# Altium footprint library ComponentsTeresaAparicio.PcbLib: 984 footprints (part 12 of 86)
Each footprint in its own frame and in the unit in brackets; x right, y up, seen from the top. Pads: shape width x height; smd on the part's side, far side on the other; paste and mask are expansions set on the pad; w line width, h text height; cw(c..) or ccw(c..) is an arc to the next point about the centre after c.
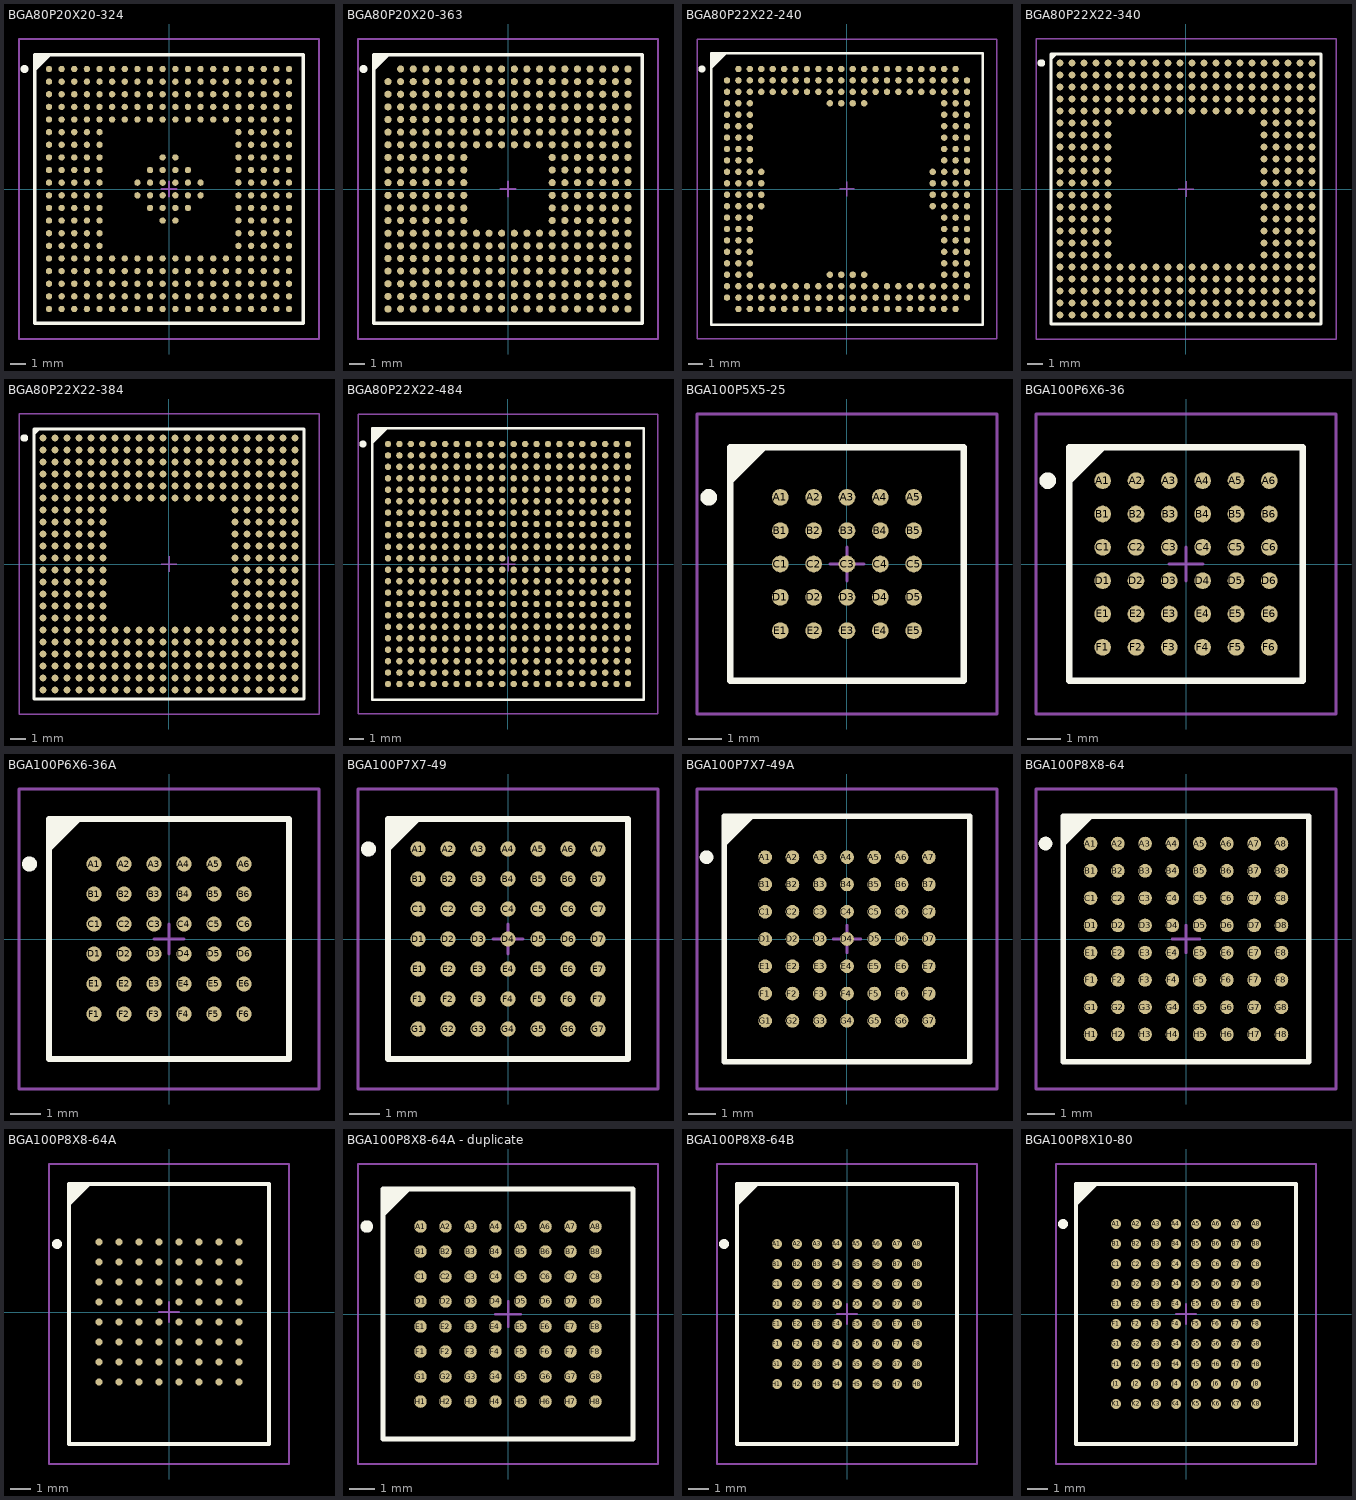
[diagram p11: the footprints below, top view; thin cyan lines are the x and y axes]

## BGA80P20X20-324 [mm] "324-Ball Chip Array Ball Grid Array"
height 1.7
pads (324):
  round 0.4 smd: A1(-7.6,7.6) A2(-6.8,7.6) A3(-6,7.6) A4(-5.2,7.6) A5(-4.4,7.6) A6(-3.6,7.6) A7(-2.8,7.6) A8(-2,7.6) A9(-1.2,7.6) A10(-0.4,7.6) A11(0.4,7.6) A12(1.2,7.6) A13(2,7.6) A14(2.8,7.6) A15(3.6,7.6) A16(4.4,7.6) A17(5.2,7.6) A18(6,7.6) A19(6.8,7.6) A20(7.6,7.6) B1(-7.6,6.8) B2(-6.8,6.8) B3(-6,6.8) B4(-5.2,6.8) B5(-4.4,6.8) B6(-3.6,6.8) B7(-2.8,6.8) B8(-2,6.8) B9(-1.2,6.8) B10(-0.4,6.8) B11(0.4,6.8) B12(1.2,6.8) B13(2,6.8) B14(2.8,6.8) B15(3.6,6.8) B16(4.4,6.8) B17(5.2,6.8) B18(6,6.8) B19(6.8,6.8) B20(7.6,6.8) C1(-7.6,6) C2(-6.8,6) C3(-6,6) C4(-5.2,6) C5(-4.4,6) C6(-3.6,6) C7(-2.8,6) C8(-2,6) C9(-1.2,6) C10(-0.4,6) C11(0.4,6) C12(1.2,6) C13(2,6) C14(2.8,6) C15(3.6,6) C16(4.4,6) C17(5.2,6) C18(6,6) C19(6.8,6) C20(7.6,6) D1(-7.6,5.2) D2(-6.8,5.2) D3(-6,5.2) D4(-5.2,5.2) D5(-4.4,5.2) D6(-3.6,5.2) D7(-2.8,5.2) D8(-2,5.2) D9(-1.2,5.2) D10(-0.4,5.2) D11(0.4,5.2) D12(1.2,5.2) D13(2,5.2) D14(2.8,5.2) D15(3.6,5.2) D16(4.4,5.2) D17(5.2,5.2) D18(6,5.2) D19(6.8,5.2) D20(7.6,5.2) E1(-7.6,4.4) E2(-6.8,4.4) E3(-6,4.4) E4(-5.2,4.4) E5(-4.4,4.4) E6(-3.6,4.4) E7(-2.8,4.4) E8(-2,4.4) E9(-1.2,4.4) E10(-0.4,4.4) E11(0.4,4.4) E12(1.2,4.4) E13(2,4.4) E14(2.8,4.4) E15(3.6,4.4) E16(4.4,4.4) E17(5.2,4.4) E18(6,4.4) E19(6.8,4.4) E20(7.6,4.4) F1(-7.6,3.6) F2(-6.8,3.6) F3(-6,3.6) F4(-5.2,3.6) F5(-4.4,3.6) F16(4.4,3.6) F17(5.2,3.6) F18(6,3.6) F19(6.8,3.6) F20(7.6,3.6) G1(-7.6,2.8) G2(-6.8,2.8) G3(-6,2.8) G4(-5.2,2.8) G5(-4.4,2.8) G16(4.4,2.8) G17(5.2,2.8) G18(6,2.8) G19(6.8,2.8) G20(7.6,2.8) H1(-7.6,2) H2(-6.8,2) H3(-6,2) H4(-5.2,2) H5(-4.4,2) H10(-0.4,2) H11(0.4,2) H16(4.4,2) H17(5.2,2) H18(6,2) H19(6.8,2) H20(7.6,2) J1(-7.6,1.2) J2(-6.8,1.2) J3(-6,1.2) J4(-5.2,1.2) J5(-4.4,1.2) J9(-1.2,1.2) J10(-0.4,1.2) J11(0.4,1.2) J12(1.2,1.2) J16(4.4,1.2) J17(5.2,1.2) J18(6,1.2) J19(6.8,1.2) J20(7.6,1.2) K1(-7.6,0.4) K2(-6.8,0.4) K3(-6,0.4) K4(-5.2,0.4) K5(-4.4,0.4) K8(-2,0.4) K9(-1.2,0.4) K10(-0.4,0.4) K11(0.4,0.4) K12(1.2,0.4) K13(2,0.4) K16(4.4,0.4) K17(5.2,0.4) K18(6,0.4) K19(6.8,0.4) K20(7.6,0.4) L1(-7.6,-0.4) L2(-6.8,-0.4) L3(-6,-0.4) L4(-5.2,-0.4) L5(-4.4,-0.4) L8(-2,-0.4) L9(-1.2,-0.4) L10(-0.4,-0.4) L11(0.4,-0.4) L12(1.2,-0.4) L13(2,-0.4) L16(4.4,-0.4) L17(5.2,-0.4) L18(6,-0.4) L19(6.8,-0.4) L20(7.6,-0.4) M1(-7.6,-1.2) M2(-6.8,-1.2) M3(-6,-1.2) M4(-5.2,-1.2) M5(-4.4,-1.2) M9(-1.2,-1.2) M10(-0.4,-1.2) M11(0.4,-1.2) M12(1.2,-1.2) M16(4.4,-1.2) M17(5.2,-1.2) M18(6,-1.2) M19(6.8,-1.2) M20(7.6,-1.2) N1(-7.6,-2) N2(-6.8,-2) N3(-6,-2) N4(-5.2,-2) N5(-4.4,-2) N10(-0.4,-2) N11(0.4,-2) N16(4.4,-2) N17(5.2,-2) N18(6,-2) N19(6.8,-2) N20(7.6,-2) P1(-7.6,-2.8) P2(-6.8,-2.8) P3(-6,-2.8) P4(-5.2,-2.8) P5(-4.4,-2.8) P16(4.4,-2.8) P17(5.2,-2.8) P18(6,-2.8) P19(6.8,-2.8) P20(7.6,-2.8) R1(-7.6,-3.6) R2(-6.8,-3.6) R3(-6,-3.6) R4(-5.2,-3.6) R5(-4.4,-3.6) R16(4.4,-3.6) R17(5.2,-3.6) R18(6,-3.6) R19(6.8,-3.6) R20(7.6,-3.6) T1(-7.6,-4.4) T2(-6.8,-4.4) T3(-6,-4.4) T4(-5.2,-4.4) T5(-4.4,-4.4) T6(-3.6,-4.4) T7(-2.8,-4.4) T8(-2,-4.4) T9(-1.2,-4.4) T10(-0.4,-4.4) T11(0.4,-4.4) T12(1.2,-4.4) T13(2,-4.4) T14(2.8,-4.4) T15(3.6,-4.4) T16(4.4,-4.4) T17(5.2,-4.4) T18(6,-4.4) T19(6.8,-4.4) T20(7.6,-4.4) U1(-7.6,-5.2) U2(-6.8,-5.2) U3(-6,-5.2) U4(-5.2,-5.2) U5(-4.4,-5.2) U6(-3.6,-5.2) U7(-2.8,-5.2) U8(-2,-5.2) U9(-1.2,-5.2) U10(-0.4,-5.2) U11(0.4,-5.2) U12(1.2,-5.2) U13(2,-5.2) U14(2.8,-5.2) U15(3.6,-5.2) U16(4.4,-5.2) U17(5.2,-5.2) U18(6,-5.2) U19(6.8,-5.2) U20(7.6,-5.2) V1(-7.6,-6) V2(-6.8,-6) V3(-6,-6) V4(-5.2,-6) V5(-4.4,-6) V6(-3.6,-6) V7(-2.8,-6) V8(-2,-6) V9(-1.2,-6) V10(-0.4,-6) V11(0.4,-6) V12(1.2,-6) V13(2,-6) V14(2.8,-6) V15(3.6,-6) V16(4.4,-6) V17(5.2,-6) V18(6,-6) V19(6.8,-6) V20(7.6,-6) W1(-7.6,-6.8) W2(-6.8,-6.8) W3(-6,-6.8) W4(-5.2,-6.8) W5(-4.4,-6.8) W6(-3.6,-6.8) W7(-2.8,-6.8) W8(-2,-6.8) W9(-1.2,-6.8) W10(-0.4,-6.8) W11(0.4,-6.8) W12(1.2,-6.8) W13(2,-6.8) W14(2.8,-6.8) W15(3.6,-6.8) W16(4.4,-6.8) W17(5.2,-6.8) W18(6,-6.8) W19(6.8,-6.8) W20(7.6,-6.8) Y1(-7.6,-7.6) Y2(-6.8,-7.6) Y3(-6,-7.6) Y4(-5.2,-7.6) Y5(-4.4,-7.6) Y6(-3.6,-7.6) Y7(-2.8,-7.6) Y8(-2,-7.6) Y9(-1.2,-7.6) Y10(-0.4,-7.6) Y11(0.4,-7.6) Y12(1.2,-7.6) Y13(2,-7.6) Y14(2.8,-7.6) Y15(3.6,-7.6) Y16(4.4,-7.6) Y17(5.2,-7.6) Y18(6,-7.6) Y19(6.8,-7.6) Y20(7.6,-7.6)
Top Overlay:
  circle w0.25: c-9.15,7.6 r0.125
  region: -7.549,8.5 -8.5,7.549 -8.5,8.5
  lines w0.2: -8.5,7.549 -7.549,8.5 ; -8.5,-8.5 -8.5,8.5 8.5,8.5 8.5,-8.5 -8.5,-8.5
Mechanical 13:
  lines w0.1: -8.5,-8.5 -8.5,8.5 8.5,8.5 8.5,-8.5 -8.5,-8.5
Mechanical 15:
  lines w0.1: -0.5,0 0.5,0 ; 0,-0.5 0,0.5 ; -9.5,-9.5 -9.5,9.5 9.5,9.5 9.5,-9.5 -9.5,-9.5
3D body: height 1.7, standoff 0, extent -8.5,-8.5 8.5,8.5

## BGA80P20X20-363 [mm] "363-Ball Flip Chip Fine Pitch Ball Grid Array (SF363)"
height 1.99
pads (363):
  round 0.45 smd: A2(-6.8,7.6) A3(-6,7.6) A4(-5.2,7.6) A5(-4.4,7.6) A6(-3.6,7.6) A7(-2.8,7.6) A8(-2,7.6) A9(-1.2,7.6) A10(-0.4,7.6) A11(0.4,7.6) A12(1.2,7.6) A13(2,7.6) A14(2.8,7.6) A15(3.6,7.6) A16(4.4,7.6) A17(5.2,7.6) A18(6,7.6) A19(6.8,7.6) A20(7.6,7.6) B1(-7.6,6.8) B2(-6.8,6.8) B3(-6,6.8) B4(-5.2,6.8) B5(-4.4,6.8) B6(-3.6,6.8) B7(-2.8,6.8) B8(-2,6.8) B9(-1.2,6.8) B10(-0.4,6.8) B11(0.4,6.8) B12(1.2,6.8) B13(2,6.8) B14(2.8,6.8) B15(3.6,6.8) B16(4.4,6.8) B17(5.2,6.8) B18(6,6.8) B19(6.8,6.8) B20(7.6,6.8) C1(-7.6,6) C2(-6.8,6) C3(-6,6) C4(-5.2,6) C5(-4.4,6) C6(-3.6,6) C7(-2.8,6) C8(-2,6) C9(-1.2,6) C10(-0.4,6) C11(0.4,6) C12(1.2,6) C13(2,6) C14(2.8,6) C15(3.6,6) C16(4.4,6) C17(5.2,6) C18(6,6) C19(6.8,6) C20(7.6,6) D1(-7.6,5.2) D2(-6.8,5.2) D3(-6,5.2) D4(-5.2,5.2) D5(-4.4,5.2) D6(-3.6,5.2) D7(-2.8,5.2) D8(-2,5.2) D9(-1.2,5.2) D10(-0.4,5.2) D11(0.4,5.2) D12(1.2,5.2) D13(2,5.2) D14(2.8,5.2) D15(3.6,5.2) D16(4.4,5.2) D17(5.2,5.2) D18(6,5.2) D19(6.8,5.2) D20(7.6,5.2) E1(-7.6,4.4) E2(-6.8,4.4) E3(-6,4.4) E4(-5.2,4.4) E5(-4.4,4.4) E6(-3.6,4.4) E7(-2.8,4.4) E8(-2,4.4) E9(-1.2,4.4) E10(-0.4,4.4) E11(0.4,4.4) E12(1.2,4.4) E13(2,4.4) E14(2.8,4.4) E15(3.6,4.4) E16(4.4,4.4) E17(5.2,4.4) E18(6,4.4) E19(6.8,4.4) E20(7.6,4.4) F1(-7.6,3.6) F2(-6.8,3.6) F3(-6,3.6) F4(-5.2,3.6) F5(-4.4,3.6) F6(-3.6,3.6) F7(-2.8,3.6) F8(-2,3.6) F9(-1.2,3.6) F10(-0.4,3.6) F11(0.4,3.6) F12(1.2,3.6) F13(2,3.6) F14(2.8,3.6) F15(3.6,3.6) F16(4.4,3.6) F17(5.2,3.6) F18(6,3.6) F19(6.8,3.6) F20(7.6,3.6) G1(-7.6,2.8) G2(-6.8,2.8) G3(-6,2.8) G4(-5.2,2.8) G5(-4.4,2.8) G6(-3.6,2.8) G7(-2.8,2.8) G8(-2,2.8) G9(-1.2,2.8) G10(-0.4,2.8) G11(0.4,2.8) G12(1.2,2.8) G13(2,2.8) G14(2.8,2.8) G15(3.6,2.8) G16(4.4,2.8) G17(5.2,2.8) G18(6,2.8) G19(6.8,2.8) G20(7.6,2.8) H1(-7.6,2) H2(-6.8,2) H3(-6,2) H4(-5.2,2) H5(-4.4,2) H6(-3.6,2) H7(-2.8,2) H14(2.8,2) H15(3.6,2) H16(4.4,2) H17(5.2,2) H18(6,2) H19(6.8,2) H20(7.6,2) J1(-7.6,1.2) J2(-6.8,1.2) J3(-6,1.2) J4(-5.2,1.2) J5(-4.4,1.2) J6(-3.6,1.2) J7(-2.8,1.2) J14(2.8,1.2) J15(3.6,1.2) J16(4.4,1.2) J17(5.2,1.2) J18(6,1.2) J19(6.8,1.2) J20(7.6,1.2) K1(-7.6,0.4) K2(-6.8,0.4) K3(-6,0.4) K4(-5.2,0.4) K5(-4.4,0.4) K6(-3.6,0.4) K7(-2.8,0.4) K14(2.8,0.4) K15(3.6,0.4) K16(4.4,0.4) K17(5.2,0.4) K18(6,0.4) K19(6.8,0.4) K20(7.6,0.4) L1(-7.6,-0.4) L2(-6.8,-0.4) L3(-6,-0.4) L4(-5.2,-0.4) L5(-4.4,-0.4) L6(-3.6,-0.4) L7(-2.8,-0.4) L14(2.8,-0.4) L15(3.6,-0.4) L16(4.4,-0.4) L17(5.2,-0.4) L18(6,-0.4) L19(6.8,-0.4) L20(7.6,-0.4) M1(-7.6,-1.2) M2(-6.8,-1.2) M3(-6,-1.2) M4(-5.2,-1.2) M5(-4.4,-1.2) M6(-3.6,-1.2) M7(-2.8,-1.2) M14(2.8,-1.2) M15(3.6,-1.2) M16(4.4,-1.2) M17(5.2,-1.2) M18(6,-1.2) M19(6.8,-1.2) M20(7.6,-1.2) N1(-7.6,-2) N2(-6.8,-2) N3(-6,-2) N4(-5.2,-2) N5(-4.4,-2) N6(-3.6,-2) N7(-2.8,-2) N14(2.8,-2) N15(3.6,-2) N16(4.4,-2) N17(5.2,-2) N18(6,-2) N19(6.8,-2) N20(7.6,-2) P1(-7.6,-2.8) P2(-6.8,-2.8) P3(-6,-2.8) P4(-5.2,-2.8) P5(-4.4,-2.8) P6(-3.6,-2.8) P7(-2.8,-2.8) P8(-2,-2.8) P9(-1.2,-2.8) P10(-0.4,-2.8) P11(0.4,-2.8) P12(1.2,-2.8) P13(2,-2.8) P14(2.8,-2.8) P15(3.6,-2.8) P16(4.4,-2.8) P17(5.2,-2.8) P18(6,-2.8) P19(6.8,-2.8) P20(7.6,-2.8) R1(-7.6,-3.6) R2(-6.8,-3.6) R3(-6,-3.6) R4(-5.2,-3.6) R5(-4.4,-3.6) R6(-3.6,-3.6) R7(-2.8,-3.6) R8(-2,-3.6) R9(-1.2,-3.6) R10(-0.4,-3.6) R11(0.4,-3.6) R12(1.2,-3.6) R13(2,-3.6) R14(2.8,-3.6) R15(3.6,-3.6) R16(4.4,-3.6) R17(5.2,-3.6) R18(6,-3.6) R19(6.8,-3.6) R20(7.6,-3.6) T1(-7.6,-4.4) T2(-6.8,-4.4) T3(-6,-4.4) T4(-5.2,-4.4) T5(-4.4,-4.4) T6(-3.6,-4.4) T7(-2.8,-4.4) T8(-2,-4.4) T9(-1.2,-4.4) T10(-0.4,-4.4) T11(0.4,-4.4) T12(1.2,-4.4) T13(2,-4.4) T14(2.8,-4.4) T15(3.6,-4.4) T16(4.4,-4.4) T17(5.2,-4.4) T18(6,-4.4) T19(6.8,-4.4) T20(7.6,-4.4) U1(-7.6,-5.2) U2(-6.8,-5.2) U3(-6,-5.2) U4(-5.2,-5.2) U5(-4.4,-5.2) U6(-3.6,-5.2) U7(-2.8,-5.2) U8(-2,-5.2) U9(-1.2,-5.2) U10(-0.4,-5.2) U11(0.4,-5.2) U12(1.2,-5.2) U13(2,-5.2) U14(2.8,-5.2) U15(3.6,-5.2) U16(4.4,-5.2) U17(5.2,-5.2) U18(6,-5.2) U19(6.8,-5.2) U20(7.6,-5.2) V1(-7.6,-6) V2(-6.8,-6) V3(-6,-6) V4(-5.2,-6) V5(-4.4,-6) V6(-3.6,-6) V7(-2.8,-6) V8(-2,-6) V9(-1.2,-6) V10(-0.4,-6) V11(0.4,-6) V12(1.2,-6) V13(2,-6) V14(2.8,-6) V15(3.6,-6) V16(4.4,-6) V17(5.2,-6) V18(6,-6) V19(6.8,-6) V20(7.6,-6) W1(-7.6,-6.8) W2(-6.8,-6.8) W3(-6,-6.8) W4(-5.2,-6.8) W5(-4.4,-6.8) W6(-3.6,-6.8) W7(-2.8,-6.8) W8(-2,-6.8) W9(-1.2,-6.8) W10(-0.4,-6.8) W11(0.4,-6.8) W12(1.2,-6.8) W13(2,-6.8) W14(2.8,-6.8) W15(3.6,-6.8) W16(4.4,-6.8) W17(5.2,-6.8) W18(6,-6.8) W19(6.8,-6.8) W20(7.6,-6.8) Y1(-7.6,-7.6) Y2(-6.8,-7.6) Y3(-6,-7.6) Y4(-5.2,-7.6) Y5(-4.4,-7.6) Y6(-3.6,-7.6) Y7(-2.8,-7.6) Y8(-2,-7.6) Y9(-1.2,-7.6) Y10(-0.4,-7.6) Y11(0.4,-7.6) Y12(1.2,-7.6) Y13(2,-7.6) Y14(2.8,-7.6) Y15(3.6,-7.6) Y16(4.4,-7.6) Y17(5.2,-7.6) Y18(6,-7.6) Y19(6.8,-7.6) Y20(7.6,-7.6)
Top Overlay:
  circle w0.25: c-9.15,7.6 r0.125
  region: -7.584,8.5 -8.5,7.584 -8.5,8.5
  lines w0.2: -8.5,7.584 -7.584,8.5 ; -8.5,-8.5 -8.5,8.5 8.5,8.5 8.5,-8.5 -8.5,-8.5
Mechanical 13:
  lines w0.1: -8.5,-8.5 -8.5,8.5 8.5,8.5 8.5,-8.5 -8.5,-8.5
Mechanical 15:
  lines w0.1: -0.5,0 0.5,0 ; 0,-0.5 0,0.5 ; -9.5,-9.5 -9.5,9.5 9.5,9.5 9.5,-9.5 -9.5,-9.5
3D body: height 1.99, standoff 0, extent -8.5,-8.5 8.5,8.5

## BGA80P22X22-240 [mm] "BGA, 240-Leads, Body 19x19mm, Pitch 0.8mm"
height 1.58
pads (240):
  round 0.45 smd: A2(-7.6,8.4) A3(-6.8,8.4) A4(-6,8.4) A5(-5.2,8.4) A6(-4.4,8.4) A7(-3.6,8.4) A8(-2.8,8.4) A9(-2,8.4) A10(-1.2,8.4) A11(-0.4,8.4) A12(0.4,8.4) A13(1.2,8.4) A14(2,8.4) A15(2.8,8.4) A16(3.6,8.4) A17(4.4,8.4) A18(5.2,8.4) A19(6,8.4) A20(6.8,8.4) A21(7.6,8.4) AA1(-8.4,-7.6) AA2(-7.6,-7.6) AA3(-6.8,-7.6) AA4(-6,-7.6) AA5(-5.2,-7.6) AA6(-4.4,-7.6) AA7(-3.6,-7.6) AA8(-2.8,-7.6) AA9(-2,-7.6) AA10(-1.2,-7.6) AA11(-0.4,-7.6) AA12(0.4,-7.6) AA13(1.2,-7.6) AA14(2,-7.6) AA15(2.8,-7.6) AA16(3.6,-7.6) AA17(4.4,-7.6) AA18(5.2,-7.6) AA19(6,-7.6) AA20(6.8,-7.6) AA21(7.6,-7.6) AA22(8.4,-7.6) AB2(-7.6,-8.4) AB3(-6.8,-8.4) AB4(-6,-8.4) AB5(-5.2,-8.4) AB6(-4.4,-8.4) AB7(-3.6,-8.4) AB8(-2.8,-8.4) AB9(-2,-8.4) AB10(-1.2,-8.4) AB11(-0.4,-8.4) AB12(0.4,-8.4) AB13(1.2,-8.4) AB14(2,-8.4) AB15(2.8,-8.4) AB16(3.6,-8.4) AB17(4.4,-8.4) AB18(5.2,-8.4) AB19(6,-8.4) AB20(6.8,-8.4) AB21(7.6,-8.4) B1(-8.4,7.6) B2(-7.6,7.6) B3(-6.8,7.6) B4(-6,7.6) B5(-5.2,7.6) B6(-4.4,7.6) B7(-3.6,7.6) B8(-2.8,7.6) B9(-2,7.6) B10(-1.2,7.6) B11(-0.4,7.6) B12(0.4,7.6) B13(1.2,7.6) B14(2,7.6) B15(2.8,7.6) B16(3.6,7.6) B17(4.4,7.6) B18(5.2,7.6) B19(6,7.6) B20(6.8,7.6) B21(7.6,7.6) B22(8.4,7.6) C1(-8.4,6.8) C2(-7.6,6.8) C3(-6.8,6.8) C4(-6,6.8) C5(-5.2,6.8) C6(-4.4,6.8) C7(-3.6,6.8) C8(-2.8,6.8) C9(-2,6.8) C10(-1.2,6.8) C11(-0.4,6.8) C12(0.4,6.8) C13(1.2,6.8) C14(2,6.8) C15(2.8,6.8) C16(3.6,6.8) C17(4.4,6.8) C18(5.2,6.8) C19(6,6.8) C20(6.8,6.8) C21(7.6,6.8) C22(8.4,6.8) D1(-8.4,6) D2(-7.6,6) D3(-6.8,6) D10(-1.2,6) D11(-0.4,6) D12(0.4,6) D13(1.2,6) D20(6.8,6) D21(7.6,6) D22(8.4,6) E1(-8.4,5.2) E2(-7.6,5.2) E3(-6.8,5.2) E20(6.8,5.2) E21(7.6,5.2) E22(8.4,5.2) F1(-8.4,4.4) F2(-7.6,4.4) F3(-6.8,4.4) F20(6.8,4.4) F21(7.6,4.4) F22(8.4,4.4) G1(-8.4,3.6) G2(-7.6,3.6) G3(-6.8,3.6) G20(6.8,3.6) G21(7.6,3.6) G22(8.4,3.6) H1(-8.4,2.8) H2(-7.6,2.8) H3(-6.8,2.8) H20(6.8,2.8) H21(7.6,2.8) H22(8.4,2.8) J1(-8.4,2) J2(-7.6,2) J3(-6.8,2) J20(6.8,2) J21(7.6,2) J22(8.4,2) K1(-8.4,1.2) K2(-7.6,1.2) K3(-6.8,1.2) K4(-6,1.2) K19(6,1.2) K20(6.8,1.2) K21(7.6,1.2) K22(8.4,1.2) L1(-8.4,0.4) L2(-7.6,0.4) L3(-6.8,0.4) L4(-6,0.4) L19(6,0.4) L20(6.8,0.4) L21(7.6,0.4) L22(8.4,0.4) M1(-8.4,-0.4) M2(-7.6,-0.4) M3(-6.8,-0.4) M4(-6,-0.4) M19(6,-0.4) M20(6.8,-0.4) M21(7.6,-0.4) M22(8.4,-0.4) N1(-8.4,-1.2) N2(-7.6,-1.2) N3(-6.8,-1.2) N4(-6,-1.2) N19(6,-1.2) N20(6.8,-1.2) N21(7.6,-1.2) N22(8.4,-1.2) P1(-8.4,-2) P2(-7.6,-2) P3(-6.8,-2) P20(6.8,-2) P21(7.6,-2) P22(8.4,-2) R1(-8.4,-2.8) R2(-7.6,-2.8) R3(-6.8,-2.8) R20(6.8,-2.8) R21(7.6,-2.8) R22(8.4,-2.8) T1(-8.4,-3.6) T2(-7.6,-3.6) T3(-6.8,-3.6) T20(6.8,-3.6) T21(7.6,-3.6) T22(8.4,-3.6) U1(-8.4,-4.4) U2(-7.6,-4.4) U3(-6.8,-4.4) U20(6.8,-4.4) U21(7.6,-4.4) U22(8.4,-4.4) V1(-8.4,-5.2) V2(-7.6,-5.2) V3(-6.8,-5.2) V20(6.8,-5.2) V21(7.6,-5.2) V22(8.4,-5.2) W1(-8.4,-6) W2(-7.6,-6) W3(-6.8,-6) W10(-1.2,-6) W11(-0.4,-6) W12(0.4,-6) W13(1.2,-6) W20(6.8,-6) W21(7.6,-6) W22(8.4,-6) Y1(-8.4,-6.8) Y2(-7.6,-6.8) Y3(-6.8,-6.8) Y4(-6,-6.8) Y5(-5.2,-6.8) Y6(-4.4,-6.8) Y7(-3.6,-6.8) Y8(-2.8,-6.8) Y9(-2,-6.8) Y10(-1.2,-6.8) Y11(-0.4,-6.8) Y12(0.4,-6.8) Y13(1.2,-6.8) Y14(2,-6.8) Y15(2.8,-6.8) Y16(3.6,-6.8) Y17(4.4,-6.8) Y18(5.2,-6.8) Y19(6,-6.8) Y20(6.8,-6.8) Y21(7.6,-6.8) Y22(8.4,-6.8)
Top Overlay:
  circle w0.25: c-10.15,8.4 r0.125
  region: -8.5,9.5 -9.5,8.5 -9.5,9.5
  lines w0.2: -9.5,8.5 -8.5,9.5 ; -9.5,-9.5 9.5,-9.5 9.5,9.5 -9.5,9.5 -9.5,-9.5
Mechanical 13:
  lines w0.1: -9.5,-9.5 9.5,-9.5 9.5,9.5 -9.5,9.5 -9.5,-9.5
Mechanical 15:
  lines w0.1: -0.5,0 0.5,0 ; 0,-0.5 0,0.5 ; -10.5,-10.5 10.5,-10.5 10.5,10.5 -10.5,10.5 -10.5,-10.5
3D body: height 1.58, standoff 0.29, extent -9.5,-9.5 9.5,9.5

## BGA80P22X22-340 [mm] "340-Ball Ball Grid Array 0.8 mm Pitch"
height 2.8
pads (340):
  round 0.45 smd: A1(-8.4,8.4) A2(-7.6,8.4) A3(-6.8,8.4) A4(-6,8.4) A5(-5.2,8.4) A6(-4.4,8.4) A7(-3.6,8.4) A8(-2.8,8.4) A9(-2,8.4) A10(-1.2,8.4) A11(-0.4,8.4) A12(0.4,8.4) A13(1.2,8.4) A14(2,8.4) A15(2.8,8.4) A16(3.6,8.4) A17(4.4,8.4) A18(5.2,8.4) A19(6,8.4) A20(6.8,8.4) A21(7.6,8.4) A22(8.4,8.4) AA1(-8.4,-7.6) AA2(-7.6,-7.6) AA3(-6.8,-7.6) AA4(-6,-7.6) AA5(-5.2,-7.6) AA6(-4.4,-7.6) AA7(-3.6,-7.6) AA8(-2.8,-7.6) AA9(-2,-7.6) AA10(-1.2,-7.6) AA11(-0.4,-7.6) AA12(0.4,-7.6) AA13(1.2,-7.6) AA14(2,-7.6) AA15(2.8,-7.6) AA16(3.6,-7.6) AA17(4.4,-7.6) AA18(5.2,-7.6) AA19(6,-7.6) AA20(6.8,-7.6) AA21(7.6,-7.6) AA22(8.4,-7.6) AB1(-8.4,-8.4) AB2(-7.6,-8.4) AB3(-6.8,-8.4) AB4(-6,-8.4) AB5(-5.2,-8.4) AB6(-4.4,-8.4) AB7(-3.6,-8.4) AB8(-2.8,-8.4) AB9(-2,-8.4) AB10(-1.2,-8.4) AB11(-0.4,-8.4) AB12(0.4,-8.4) AB13(1.2,-8.4) AB14(2,-8.4) AB15(2.8,-8.4) AB16(3.6,-8.4) AB17(4.4,-8.4) AB18(5.2,-8.4) AB19(6,-8.4) AB20(6.8,-8.4) AB21(7.6,-8.4) AB22(8.4,-8.4) B1(-8.4,7.6) B2(-7.6,7.6) B3(-6.8,7.6) B4(-6,7.6) B5(-5.2,7.6) B6(-4.4,7.6) B7(-3.6,7.6) B8(-2.8,7.6) B9(-2,7.6) B10(-1.2,7.6) B11(-0.4,7.6) B12(0.4,7.6) B13(1.2,7.6) B14(2,7.6) B15(2.8,7.6) B16(3.6,7.6) B17(4.4,7.6) B18(5.2,7.6) B19(6,7.6) B20(6.8,7.6) B21(7.6,7.6) B22(8.4,7.6) C1(-8.4,6.8) C2(-7.6,6.8) C3(-6.8,6.8) C4(-6,6.8) C5(-5.2,6.8) C6(-4.4,6.8) C7(-3.6,6.8) C8(-2.8,6.8) C9(-2,6.8) C10(-1.2,6.8) C11(-0.4,6.8) C12(0.4,6.8) C13(1.2,6.8) C14(2,6.8) C15(2.8,6.8) C16(3.6,6.8) C17(4.4,6.8) C18(5.2,6.8) C19(6,6.8) C20(6.8,6.8) C21(7.6,6.8) C22(8.4,6.8) D1(-8.4,6) D2(-7.6,6) D3(-6.8,6) D4(-6,6) D5(-5.2,6) D6(-4.4,6) D7(-3.6,6) D8(-2.8,6) D9(-2,6) D10(-1.2,6) D11(-0.4,6) D12(0.4,6) D13(1.2,6) D14(2,6) D15(2.8,6) D16(3.6,6) D17(4.4,6) D18(5.2,6) D19(6,6) D20(6.8,6) D21(7.6,6) D22(8.4,6) E1(-8.4,5.2) E2(-7.6,5.2) E3(-6.8,5.2) E4(-6,5.2) E5(-5.2,5.2) E6(-4.4,5.2) E7(-3.6,5.2) E8(-2.8,5.2) E9(-2,5.2) E10(-1.2,5.2) E11(-0.4,5.2) E12(0.4,5.2) E13(1.2,5.2) E14(2,5.2) E15(2.8,5.2) E16(3.6,5.2) E17(4.4,5.2) E18(5.2,5.2) E19(6,5.2) E20(6.8,5.2) E21(7.6,5.2) E22(8.4,5.2) F1(-8.4,4.4) F2(-7.6,4.4) F3(-6.8,4.4) F4(-6,4.4) F5(-5.2,4.4) F18(5.2,4.4) F19(6,4.4) F20(6.8,4.4) F21(7.6,4.4) F22(8.4,4.4) G1(-8.4,3.6) G2(-7.6,3.6) G3(-6.8,3.6) G4(-6,3.6) G5(-5.2,3.6) G18(5.2,3.6) G19(6,3.6) G20(6.8,3.6) G21(7.6,3.6) G22(8.4,3.6) H1(-8.4,2.8) H2(-7.6,2.8) H3(-6.8,2.8) H4(-6,2.8) H5(-5.2,2.8) H18(5.2,2.8) H19(6,2.8) H20(6.8,2.8) H21(7.6,2.8) H22(8.4,2.8) J1(-8.4,2) J2(-7.6,2) J3(-6.8,2) J4(-6,2) J5(-5.2,2) J18(5.2,2) J19(6,2) J20(6.8,2) J21(7.6,2) J22(8.4,2) K1(-8.4,1.2) K2(-7.6,1.2) K3(-6.8,1.2) K4(-6,1.2) K5(-5.2,1.2) K18(5.2,1.2) K19(6,1.2) K20(6.8,1.2) K21(7.6,1.2) K22(8.4,1.2) L1(-8.4,0.4) L2(-7.6,0.4) L3(-6.8,0.4) L4(-6,0.4) L5(-5.2,0.4) L18(5.2,0.4) L19(6,0.4) L20(6.8,0.4) L21(7.6,0.4) L22(8.4,0.4) M1(-8.4,-0.4) M2(-7.6,-0.4) M3(-6.8,-0.4) M4(-6,-0.4) M5(-5.2,-0.4) M18(5.2,-0.4) M19(6,-0.4) M20(6.8,-0.4) M21(7.6,-0.4) M22(8.4,-0.4) N1(-8.4,-1.2) N2(-7.6,-1.2) N3(-6.8,-1.2) N4(-6,-1.2) N5(-5.2,-1.2) N18(5.2,-1.2) N19(6,-1.2) N20(6.8,-1.2) N21(7.6,-1.2) N22(8.4,-1.2) P1(-8.4,-2) P2(-7.6,-2) P3(-6.8,-2) P4(-6,-2) P5(-5.2,-2) P18(5.2,-2) P19(6,-2) P20(6.8,-2) P21(7.6,-2) P22(8.4,-2) R1(-8.4,-2.8) R2(-7.6,-2.8) R3(-6.8,-2.8) R4(-6,-2.8) R5(-5.2,-2.8) R18(5.2,-2.8) R19(6,-2.8) R20(6.8,-2.8) R21(7.6,-2.8) R22(8.4,-2.8) T1(-8.4,-3.6) T2(-7.6,-3.6) T3(-6.8,-3.6) T4(-6,-3.6) T5(-5.2,-3.6) T18(5.2,-3.6) T19(6,-3.6) T20(6.8,-3.6) T21(7.6,-3.6) T22(8.4,-3.6) U1(-8.4,-4.4) U2(-7.6,-4.4) U3(-6.8,-4.4) U4(-6,-4.4) U5(-5.2,-4.4) U18(5.2,-4.4) U19(6,-4.4) U20(6.8,-4.4) U21(7.6,-4.4) U22(8.4,-4.4) V1(-8.4,-5.2) V2(-7.6,-5.2) V3(-6.8,-5.2) V4(-6,-5.2) V5(-5.2,-5.2) V6(-4.4,-5.2) V7(-3.6,-5.2) V8(-2.8,-5.2) V9(-2,-5.2) V10(-1.2,-5.2) V11(-0.4,-5.2) V12(0.4,-5.2) V13(1.2,-5.2) V14(2,-5.2) V15(2.8,-5.2) V16(3.6,-5.2) V17(4.4,-5.2) V18(5.2,-5.2) V19(6,-5.2) V20(6.8,-5.2) V21(7.6,-5.2) V22(8.4,-5.2) W1(-8.4,-6) W2(-7.6,-6) W3(-6.8,-6) W4(-6,-6) W5(-5.2,-6) W6(-4.4,-6) W7(-3.6,-6) W8(-2.8,-6) W9(-2,-6) W10(-1.2,-6) W11(-0.4,-6) W12(0.4,-6) W13(1.2,-6) W14(2,-6) W15(2.8,-6) W16(3.6,-6) W17(4.4,-6) W18(5.2,-6) W19(6,-6) W20(6.8,-6) W21(7.6,-6) W22(8.4,-6) Y1(-8.4,-6.8) Y2(-7.6,-6.8) Y3(-6.8,-6.8) Y4(-6,-6.8) Y5(-5.2,-6.8) Y6(-4.4,-6.8) Y7(-3.6,-6.8) Y8(-2.8,-6.8) Y9(-2,-6.8) Y10(-1.2,-6.8) Y11(-0.4,-6.8) Y12(0.4,-6.8) Y13(1.2,-6.8) Y14(2,-6.8) Y15(2.8,-6.8) Y16(3.6,-6.8) Y17(4.4,-6.8) Y18(5.2,-6.8) Y19(6,-6.8) Y20(6.8,-6.8) Y21(7.6,-6.8) Y22(8.4,-6.8)
Top Overlay:
  circle w0.25: c-9.65,8.4 r0.125
  region: -8.684,9 -9,8.684 -9,9
  lines w0.2: -9,8.684 -8.684,9 ; -9,-9 9,-9 9,9 -9,9 -9,-9
Mechanical 13:
  lines w0.1: -9,-9 9,-9 9,9 -9,9 -9,-9
Mechanical 15:
  lines w0.1: -0.5,0 0.5,0 ; 0,-0.5 0,0.5 ; -10,-10 10,-10 10,10 -10,10 -10,-10
3D body: height 2.8, standoff 0, extent -9,-9 9,9

## BGA80P22X22-384 [mm] "384-Ball Ball Grid Array 0.8 mm Pitch"
height 2.8
pads (384):
  round 0.45 smd: A1(-8.4,8.4) A2(-7.6,8.4) A3(-6.8,8.4) A4(-6,8.4) A5(-5.2,8.4) A6(-4.4,8.4) A7(-3.6,8.4) A8(-2.8,8.4) A9(-2,8.4) A10(-1.2,8.4) A11(-0.4,8.4) A12(0.4,8.4) A13(1.2,8.4) A14(2,8.4) A15(2.8,8.4) A16(3.6,8.4) A17(4.4,8.4) A18(5.2,8.4) A19(6,8.4) A20(6.8,8.4) A21(7.6,8.4) A22(8.4,8.4) AA1(-8.4,-7.6) AA2(-7.6,-7.6) AA3(-6.8,-7.6) AA4(-6,-7.6) AA5(-5.2,-7.6) AA6(-4.4,-7.6) AA7(-3.6,-7.6) AA8(-2.8,-7.6) AA9(-2,-7.6) AA10(-1.2,-7.6) AA11(-0.4,-7.6) AA12(0.4,-7.6) AA13(1.2,-7.6) AA14(2,-7.6) AA15(2.8,-7.6) AA16(3.6,-7.6) AA17(4.4,-7.6) AA18(5.2,-7.6) AA19(6,-7.6) AA20(6.8,-7.6) AA21(7.6,-7.6) AA22(8.4,-7.6) AB1(-8.4,-8.4) AB2(-7.6,-8.4) AB3(-6.8,-8.4) AB4(-6,-8.4) AB5(-5.2,-8.4) AB6(-4.4,-8.4) AB7(-3.6,-8.4) AB8(-2.8,-8.4) AB9(-2,-8.4) AB10(-1.2,-8.4) AB11(-0.4,-8.4) AB12(0.4,-8.4) AB13(1.2,-8.4) AB14(2,-8.4) AB15(2.8,-8.4) AB16(3.6,-8.4) AB17(4.4,-8.4) AB18(5.2,-8.4) AB19(6,-8.4) AB20(6.8,-8.4) AB21(7.6,-8.4) AB22(8.4,-8.4) B1(-8.4,7.6) B2(-7.6,7.6) B3(-6.8,7.6) B4(-6,7.6) B5(-5.2,7.6) B6(-4.4,7.6) B7(-3.6,7.6) B8(-2.8,7.6) B9(-2,7.6) B10(-1.2,7.6) B11(-0.4,7.6) B12(0.4,7.6) B13(1.2,7.6) B14(2,7.6) B15(2.8,7.6) B16(3.6,7.6) B17(4.4,7.6) B18(5.2,7.6) B19(6,7.6) B20(6.8,7.6) B21(7.6,7.6) B22(8.4,7.6) C1(-8.4,6.8) C2(-7.6,6.8) C3(-6.8,6.8) C4(-6,6.8) C5(-5.2,6.8) C6(-4.4,6.8) C7(-3.6,6.8) C8(-2.8,6.8) C9(-2,6.8) C10(-1.2,6.8) C11(-0.4,6.8) C12(0.4,6.8) C13(1.2,6.8) C14(2,6.8) C15(2.8,6.8) C16(3.6,6.8) C17(4.4,6.8) C18(5.2,6.8) C19(6,6.8) C20(6.8,6.8) C21(7.6,6.8) C22(8.4,6.8) D1(-8.4,6) D2(-7.6,6) D3(-6.8,6) D4(-6,6) D5(-5.2,6) D6(-4.4,6) D7(-3.6,6) D8(-2.8,6) D9(-2,6) D10(-1.2,6) D11(-0.4,6) D12(0.4,6) D13(1.2,6) D14(2,6) D15(2.8,6) D16(3.6,6) D17(4.4,6) D18(5.2,6) D19(6,6) D20(6.8,6) D21(7.6,6) D22(8.4,6) E1(-8.4,5.2) E2(-7.6,5.2) E3(-6.8,5.2) E4(-6,5.2) E5(-5.2,5.2) E6(-4.4,5.2) E7(-3.6,5.2) E8(-2.8,5.2) E9(-2,5.2) E10(-1.2,5.2) E11(-0.4,5.2) E12(0.4,5.2) E13(1.2,5.2) E14(2,5.2) E15(2.8,5.2) E16(3.6,5.2) E17(4.4,5.2) E18(5.2,5.2) E19(6,5.2) E20(6.8,5.2) E21(7.6,5.2) E22(8.4,5.2) F1(-8.4,4.4) F2(-7.6,4.4) F3(-6.8,4.4) F4(-6,4.4) F5(-5.2,4.4) F6(-4.4,4.4) F7(-3.6,4.4) F8(-2.8,4.4) F9(-2,4.4) F10(-1.2,4.4) F11(-0.4,4.4) F12(0.4,4.4) F13(1.2,4.4) F14(2,4.4) F15(2.8,4.4) F16(3.6,4.4) F17(4.4,4.4) F18(5.2,4.4) F19(6,4.4) F20(6.8,4.4) F21(7.6,4.4) F22(8.4,4.4) G1(-8.4,3.6) G2(-7.6,3.6) G3(-6.8,3.6) G4(-6,3.6) G5(-5.2,3.6) G6(-4.4,3.6) G17(4.4,3.6) G18(5.2,3.6) G19(6,3.6) G20(6.8,3.6) G21(7.6,3.6) G22(8.4,3.6) H1(-8.4,2.8) H2(-7.6,2.8) H3(-6.8,2.8) H4(-6,2.8) H5(-5.2,2.8) H6(-4.4,2.8) H17(4.4,2.8) H18(5.2,2.8) H19(6,2.8) H20(6.8,2.8) H21(7.6,2.8) H22(8.4,2.8) J1(-8.4,2) J2(-7.6,2) J3(-6.8,2) J4(-6,2) J5(-5.2,2) J6(-4.4,2) J17(4.4,2) J18(5.2,2) J19(6,2) J20(6.8,2) J21(7.6,2) J22(8.4,2) K1(-8.4,1.2) K2(-7.6,1.2) K3(-6.8,1.2) K4(-6,1.2) K5(-5.2,1.2) K6(-4.4,1.2) K17(4.4,1.2) K18(5.2,1.2) K19(6,1.2) K20(6.8,1.2) K21(7.6,1.2) K22(8.4,1.2) L1(-8.4,0.4) L2(-7.6,0.4) L3(-6.8,0.4) L4(-6,0.4) L5(-5.2,0.4) L6(-4.4,0.4) L17(4.4,0.4) L18(5.2,0.4) L19(6,0.4) L20(6.8,0.4) L21(7.6,0.4) L22(8.4,0.4) M1(-8.4,-0.4) M2(-7.6,-0.4) M3(-6.8,-0.4) M4(-6,-0.4) M5(-5.2,-0.4) M6(-4.4,-0.4) M17(4.4,-0.4) M18(5.2,-0.4) M19(6,-0.4) M20(6.8,-0.4) M21(7.6,-0.4) M22(8.4,-0.4) N1(-8.4,-1.2) N2(-7.6,-1.2) N3(-6.8,-1.2) N4(-6,-1.2) N5(-5.2,-1.2) N6(-4.4,-1.2) N17(4.4,-1.2) N18(5.2,-1.2) N19(6,-1.2) N20(6.8,-1.2) N21(7.6,-1.2) N22(8.4,-1.2) P1(-8.4,-2) P2(-7.6,-2) P3(-6.8,-2) P4(-6,-2) P5(-5.2,-2) P6(-4.4,-2) P17(4.4,-2) P18(5.2,-2) P19(6,-2) P20(6.8,-2) P21(7.6,-2) P22(8.4,-2) R1(-8.4,-2.8) R2(-7.6,-2.8) R3(-6.8,-2.8) R4(-6,-2.8) R5(-5.2,-2.8) R6(-4.4,-2.8) R17(4.4,-2.8) R18(5.2,-2.8) R19(6,-2.8) R20(6.8,-2.8) R21(7.6,-2.8) R22(8.4,-2.8) T1(-8.4,-3.6) T2(-7.6,-3.6) T3(-6.8,-3.6) T4(-6,-3.6) T5(-5.2,-3.6) T6(-4.4,-3.6) T17(4.4,-3.6) T18(5.2,-3.6) T19(6,-3.6) T20(6.8,-3.6) T21(7.6,-3.6) T22(8.4,-3.6) U1(-8.4,-4.4) U2(-7.6,-4.4) U3(-6.8,-4.4) U4(-6,-4.4) U5(-5.2,-4.4) U6(-4.4,-4.4) U7(-3.6,-4.4) U8(-2.8,-4.4) U9(-2,-4.4) U10(-1.2,-4.4) U11(-0.4,-4.4) U12(0.4,-4.4) U13(1.2,-4.4) U14(2,-4.4) U15(2.8,-4.4) U16(3.6,-4.4) U17(4.4,-4.4) U18(5.2,-4.4) U19(6,-4.4) U20(6.8,-4.4) U21(7.6,-4.4) U22(8.4,-4.4) V1(-8.4,-5.2) V2(-7.6,-5.2) V3(-6.8,-5.2) V4(-6,-5.2) V5(-5.2,-5.2) V6(-4.4,-5.2) V7(-3.6,-5.2) V8(-2.8,-5.2) V9(-2,-5.2) V10(-1.2,-5.2) V11(-0.4,-5.2) V12(0.4,-5.2) V13(1.2,-5.2) V14(2,-5.2) V15(2.8,-5.2) V16(3.6,-5.2) V17(4.4,-5.2) V18(5.2,-5.2) V19(6,-5.2) V20(6.8,-5.2) V21(7.6,-5.2) V22(8.4,-5.2) W1(-8.4,-6) W2(-7.6,-6) W3(-6.8,-6) W4(-6,-6) W5(-5.2,-6) W6(-4.4,-6) W7(-3.6,-6) W8(-2.8,-6) W9(-2,-6) W10(-1.2,-6) W11(-0.4,-6) W12(0.4,-6) W13(1.2,-6) W14(2,-6) W15(2.8,-6) W16(3.6,-6) W17(4.4,-6) W18(5.2,-6) W19(6,-6) W20(6.8,-6) W21(7.6,-6) W22(8.4,-6) Y1(-8.4,-6.8) Y2(-7.6,-6.8) Y3(-6.8,-6.8) Y4(-6,-6.8) Y5(-5.2,-6.8) Y6(-4.4,-6.8) Y7(-3.6,-6.8) Y8(-2.8,-6.8) Y9(-2,-6.8) Y10(-1.2,-6.8) Y11(-0.4,-6.8) Y12(0.4,-6.8) Y13(1.2,-6.8) Y14(2,-6.8) Y15(2.8,-6.8) Y16(3.6,-6.8) Y17(4.4,-6.8) Y18(5.2,-6.8) Y19(6,-6.8) Y20(6.8,-6.8) Y21(7.6,-6.8) Y22(8.4,-6.8)
Top Overlay:
  circle w0.25: c-9.65,8.4 r0.125
  region: -8.684,9 -9,8.684 -9,9
  lines w0.2: -9,8.684 -8.684,9 ; -9,-9 9,-9 9,9 -9,9 -9,-9
Mechanical 13:
  lines w0.1: -9,-9 9,-9 9,9 -9,9 -9,-9
Mechanical 15:
  lines w0.1: -0.5,0 0.5,0 ; 0,-0.5 0,0.5 ; -10,-10 10,-10 10,10 -10,10 -10,-10
3D body: height 2.8, standoff 0, extent -9,-9 9,9

## BGA80P22X22-484 [mm] "BGA, 484-Leads, Body 19x19mm, Pitch 0.8mm"
height 2.2
pads (484):
  round 0.45 smd: A1(-8.4,8.4) A2(-7.6,8.4) A3(-6.8,8.4) A4(-6,8.4) A5(-5.2,8.4) A6(-4.4,8.4) A7(-3.6,8.4) A8(-2.8,8.4) A9(-2,8.4) A10(-1.2,8.4) A11(-0.4,8.4) A12(0.4,8.4) A13(1.2,8.4) A14(2,8.4) A15(2.8,8.4) A16(3.6,8.4) A17(4.4,8.4) A18(5.2,8.4) A19(6,8.4) A20(6.8,8.4) A21(7.6,8.4) A22(8.4,8.4) AA1(-8.4,-7.6) AA2(-7.6,-7.6) AA3(-6.8,-7.6) AA4(-6,-7.6) AA5(-5.2,-7.6) AA6(-4.4,-7.6) AA7(-3.6,-7.6) AA8(-2.8,-7.6) AA9(-2,-7.6) AA10(-1.2,-7.6) AA11(-0.4,-7.6) AA12(0.4,-7.6) AA13(1.2,-7.6) AA14(2,-7.6) AA15(2.8,-7.6) AA16(3.6,-7.6) AA17(4.4,-7.6) AA18(5.2,-7.6) AA19(6,-7.6) AA20(6.8,-7.6) AA21(7.6,-7.6) AA22(8.4,-7.6) AB1(-8.4,-8.4) AB2(-7.6,-8.4) AB3(-6.8,-8.4) AB4(-6,-8.4) AB5(-5.2,-8.4) AB6(-4.4,-8.4) AB7(-3.6,-8.4) AB8(-2.8,-8.4) AB9(-2,-8.4) AB10(-1.2,-8.4) AB11(-0.4,-8.4) AB12(0.4,-8.4) AB13(1.2,-8.4) AB14(2,-8.4) AB15(2.8,-8.4) AB16(3.6,-8.4) AB17(4.4,-8.4) AB18(5.2,-8.4) AB19(6,-8.4) AB20(6.8,-8.4) AB21(7.6,-8.4) AB22(8.4,-8.4) B1(-8.4,7.6) B2(-7.6,7.6) B3(-6.8,7.6) B4(-6,7.6) B5(-5.2,7.6) B6(-4.4,7.6) B7(-3.6,7.6) B8(-2.8,7.6) B9(-2,7.6) B10(-1.2,7.6) B11(-0.4,7.6) B12(0.4,7.6) B13(1.2,7.6) B14(2,7.6) B15(2.8,7.6) B16(3.6,7.6) B17(4.4,7.6) B18(5.2,7.6) B19(6,7.6) B20(6.8,7.6) B21(7.6,7.6) B22(8.4,7.6) C1(-8.4,6.8) C2(-7.6,6.8) C3(-6.8,6.8) C4(-6,6.8) C5(-5.2,6.8) C6(-4.4,6.8) C7(-3.6,6.8) C8(-2.8,6.8) C9(-2,6.8) C10(-1.2,6.8) C11(-0.4,6.8) C12(0.4,6.8) C13(1.2,6.8) C14(2,6.8) C15(2.8,6.8) C16(3.6,6.8) C17(4.4,6.8) C18(5.2,6.8) C19(6,6.8) C20(6.8,6.8) C21(7.6,6.8) C22(8.4,6.8) D1(-8.4,6) D2(-7.6,6) D3(-6.8,6) D4(-6,6) D5(-5.2,6) D6(-4.4,6) D7(-3.6,6) D8(-2.8,6) D9(-2,6) D10(-1.2,6) D11(-0.4,6) D12(0.4,6) D13(1.2,6) D14(2,6) D15(2.8,6) D16(3.6,6) D17(4.4,6) D18(5.2,6) D19(6,6) D20(6.8,6) D21(7.6,6) D22(8.4,6) E1(-8.4,5.2) E2(-7.6,5.2) E3(-6.8,5.2) E4(-6,5.2) E5(-5.2,5.2) E6(-4.4,5.2) E7(-3.6,5.2) E8(-2.8,5.2) E9(-2,5.2) E10(-1.2,5.2) E11(-0.4,5.2) E12(0.4,5.2) E13(1.2,5.2) E14(2,5.2) E15(2.8,5.2) E16(3.6,5.2) E17(4.4,5.2) E18(5.2,5.2) E19(6,5.2) E20(6.8,5.2) E21(7.6,5.2) E22(8.4,5.2) F1(-8.4,4.4) F2(-7.6,4.4) F3(-6.8,4.4) F4(-6,4.4) F5(-5.2,4.4) F6(-4.4,4.4) F7(-3.6,4.4) F8(-2.8,4.4) F9(-2,4.4) F10(-1.2,4.4) F11(-0.4,4.4) F12(0.4,4.4) F13(1.2,4.4) F14(2,4.4) F15(2.8,4.4) F16(3.6,4.4) F17(4.4,4.4) F18(5.2,4.4) F19(6,4.4) F20(6.8,4.4) F21(7.6,4.4) F22(8.4,4.4) G1(-8.4,3.6) G2(-7.6,3.6) G3(-6.8,3.6) G4(-6,3.6) G5(-5.2,3.6) G6(-4.4,3.6) G7(-3.6,3.6) G8(-2.8,3.6) G9(-2,3.6) G10(-1.2,3.6) G11(-0.4,3.6) G12(0.4,3.6) G13(1.2,3.6) G14(2,3.6) G15(2.8,3.6) G16(3.6,3.6) G17(4.4,3.6) G18(5.2,3.6) G19(6,3.6) G20(6.8,3.6) G21(7.6,3.6) G22(8.4,3.6) H1(-8.4,2.8) H2(-7.6,2.8) H3(-6.8,2.8) H4(-6,2.8) H5(-5.2,2.8) H6(-4.4,2.8) H7(-3.6,2.8) H8(-2.8,2.8) H9(-2,2.8) H10(-1.2,2.8) H11(-0.4,2.8) H12(0.4,2.8) H13(1.2,2.8) H14(2,2.8) H15(2.8,2.8) H16(3.6,2.8) H17(4.4,2.8) H18(5.2,2.8) H19(6,2.8) H20(6.8,2.8) H21(7.6,2.8) H22(8.4,2.8) J1(-8.4,2) J2(-7.6,2) J3(-6.8,2) J4(-6,2) J5(-5.2,2) J6(-4.4,2) J7(-3.6,2) J8(-2.8,2) J9(-2,2) J10(-1.2,2) J11(-0.4,2) J12(0.4,2) J13(1.2,2) J14(2,2) J15(2.8,2) J16(3.6,2) J17(4.4,2) J18(5.2,2) J19(6,2) J20(6.8,2) J21(7.6,2) J22(8.4,2) K1(-8.4,1.2) K2(-7.6,1.2) K3(-6.8,1.2) K4(-6,1.2) K5(-5.2,1.2) K6(-4.4,1.2) K7(-3.6,1.2) K8(-2.8,1.2) K9(-2,1.2) K10(-1.2,1.2) K11(-0.4,1.2) K12(0.4,1.2) K13(1.2,1.2) K14(2,1.2) K15(2.8,1.2) K16(3.6,1.2) K17(4.4,1.2) K18(5.2,1.2) K19(6,1.2) K20(6.8,1.2) K21(7.6,1.2) K22(8.4,1.2) L1(-8.4,0.4) L2(-7.6,0.4) L3(-6.8,0.4) L4(-6,0.4) L5(-5.2,0.4) L6(-4.4,0.4) L7(-3.6,0.4) L8(-2.8,0.4) L9(-2,0.4) L10(-1.2,0.4) L11(-0.4,0.4) L12(0.4,0.4) L13(1.2,0.4) L14(2,0.4) L15(2.8,0.4) L16(3.6,0.4) L17(4.4,0.4) L18(5.2,0.4) L19(6,0.4) L20(6.8,0.4) L21(7.6,0.4) L22(8.4,0.4) M1(-8.4,-0.4) M2(-7.6,-0.4) M3(-6.8,-0.4) M4(-6,-0.4) M5(-5.2,-0.4) M6(-4.4,-0.4) M7(-3.6,-0.4) M8(-2.8,-0.4) M9(-2,-0.4) M10(-1.2,-0.4) M11(-0.4,-0.4) M12(0.4,-0.4) M13(1.2,-0.4) M14(2,-0.4) M15(2.8,-0.4) M16(3.6,-0.4) M17(4.4,-0.4) M18(5.2,-0.4) M19(6,-0.4) M20(6.8,-0.4) M21(7.6,-0.4) M22(8.4,-0.4) N1(-8.4,-1.2) N2(-7.6,-1.2) N3(-6.8,-1.2) N4(-6,-1.2) N5(-5.2,-1.2) N6(-4.4,-1.2) N7(-3.6,-1.2) N8(-2.8,-1.2) N9(-2,-1.2) N10(-1.2,-1.2) N11(-0.4,-1.2) N12(0.4,-1.2) N13(1.2,-1.2) N14(2,-1.2) N15(2.8,-1.2) N16(3.6,-1.2) N17(4.4,-1.2) N18(5.2,-1.2) N19(6,-1.2) N20(6.8,-1.2) N21(7.6,-1.2) N22(8.4,-1.2) P1(-8.4,-2) P2(-7.6,-2) P3(-6.8,-2) P4(-6,-2) P5(-5.2,-2) P6(-4.4,-2) P7(-3.6,-2) P8(-2.8,-2) P9(-2,-2) P10(-1.2,-2) P11(-0.4,-2) P12(0.4,-2) P13(1.2,-2) P14(2,-2) P15(2.8,-2) P16(3.6,-2) P17(4.4,-2) P18(5.2,-2) P19(6,-2) P20(6.8,-2) P21(7.6,-2) P22(8.4,-2) R1(-8.4,-2.8) R2(-7.6,-2.8) R3(-6.8,-2.8) R4(-6,-2.8) R5(-5.2,-2.8) R6(-4.4,-2.8) R7(-3.6,-2.8) R8(-2.8,-2.8) R9(-2,-2.8) R10(-1.2,-2.8) R11(-0.4,-2.8) R12(0.4,-2.8) R13(1.2,-2.8) R14(2,-2.8) R15(2.8,-2.8) R16(3.6,-2.8) R17(4.4,-2.8) R18(5.2,-2.8) R19(6,-2.8) R20(6.8,-2.8) R21(7.6,-2.8) R22(8.4,-2.8) T1(-8.4,-3.6) T2(-7.6,-3.6) T3(-6.8,-3.6) T4(-6,-3.6) T5(-5.2,-3.6) T6(-4.4,-3.6) T7(-3.6,-3.6) T8(-2.8,-3.6) T9(-2,-3.6) T10(-1.2,-3.6) T11(-0.4,-3.6) T12(0.4,-3.6) T13(1.2,-3.6) T14(2,-3.6) T15(2.8,-3.6) T16(3.6,-3.6) T17(4.4,-3.6) T18(5.2,-3.6) T19(6,-3.6) T20(6.8,-3.6) T21(7.6,-3.6) T22(8.4,-3.6) U1(-8.4,-4.4) U2(-7.6,-4.4) U3(-6.8,-4.4) U4(-6,-4.4) U5(-5.2,-4.4) U6(-4.4,-4.4) U7(-3.6,-4.4) U8(-2.8,-4.4) U9(-2,-4.4) U10(-1.2,-4.4) U11(-0.4,-4.4) U12(0.4,-4.4) U13(1.2,-4.4) U14(2,-4.4) U15(2.8,-4.4) U16(3.6,-4.4) U17(4.4,-4.4) U18(5.2,-4.4) U19(6,-4.4) U20(6.8,-4.4) U21(7.6,-4.4) U22(8.4,-4.4) V1(-8.4,-5.2) V2(-7.6,-5.2) V3(-6.8,-5.2) V4(-6,-5.2) V5(-5.2,-5.2) V6(-4.4,-5.2) V7(-3.6,-5.2) V8(-2.8,-5.2) V9(-2,-5.2) V10(-1.2,-5.2) V11(-0.4,-5.2) V12(0.4,-5.2) V13(1.2,-5.2) V14(2,-5.2) V15(2.8,-5.2) V16(3.6,-5.2) V17(4.4,-5.2) V18(5.2,-5.2) V19(6,-5.2) V20(6.8,-5.2) V21(7.6,-5.2) V22(8.4,-5.2) W1(-8.4,-6) W2(-7.6,-6) W3(-6.8,-6) W4(-6,-6) W5(-5.2,-6) W6(-4.4,-6) W7(-3.6,-6) W8(-2.8,-6) W9(-2,-6) W10(-1.2,-6) W11(-0.4,-6) W12(0.4,-6) W13(1.2,-6) W14(2,-6) W15(2.8,-6) W16(3.6,-6) W17(4.4,-6) W18(5.2,-6) W19(6,-6) W20(6.8,-6) W21(7.6,-6) W22(8.4,-6) Y1(-8.4,-6.8) Y2(-7.6,-6.8) Y3(-6.8,-6.8) Y4(-6,-6.8) Y5(-5.2,-6.8) Y6(-4.4,-6.8) Y7(-3.6,-6.8) Y8(-2.8,-6.8) Y9(-2,-6.8) Y10(-1.2,-6.8) Y11(-0.4,-6.8) Y12(0.4,-6.8) Y13(1.2,-6.8) Y14(2,-6.8) Y15(2.8,-6.8) Y16(3.6,-6.8) Y17(4.4,-6.8) Y18(5.2,-6.8) Y19(6,-6.8) Y20(6.8,-6.8) Y21(7.6,-6.8) Y22(8.4,-6.8)
Top Overlay:
  circle w0.25: c-10.15,8.4 r0.125
  region: -8.5,9.5 -9.5,8.5 -9.5,9.5
  lines w0.2: -9.5,8.5 -8.5,9.5 ; -9.5,-9.5 9.5,-9.5 9.5,9.5 -9.5,9.5 -9.5,-9.5
Mechanical 13:
  lines w0.1: -9.5,-9.5 9.5,-9.5 9.5,9.5 -9.5,9.5 -9.5,-9.5
Mechanical 15:
  lines w0.1: -0.5,0 0.5,0 ; 0,-0.5 0,0.5 ; -10.5,-10.5 10.5,-10.5 10.5,10.5 -10.5,10.5 -10.5,-10.5
3D body: height 2.2, standoff 0, extent -9.5,-9.5 9.5,9.5

## BGA100P5X5-25 [mm] "BGA, 25-Leads, Body 7x7mm, Pitch 1mm"
height 3.5
pads (25):
  round 0.5 smd: A1(-2,2) A2(-1,2) A3(0,2) A4(1,2) A5(2,2) B1(-2,1) B2(-1,1) B3(0,1) B4(1,1) B5(2,1) C1(-2,0) C2(-1,0) C3(0,0) C4(1,0) C5(2,0) D1(-2,-1) D2(-1,-1) D3(0,-1) D4(1,-1) D5(2,-1) E1(-2,-2) E2(-1,-2) E3(0,-2) E4(1,-2) E5(2,-2)
Top Overlay:
  circle w0.25: c-4.15,2 r0.125
  region: -2.5,3.5 -3.5,2.5 -3.5,3.5
  lines w0.2: -3.5,2.5 -2.5,3.5 ; -3.5,-3.5 -3.5,3.5 3.5,3.5 3.5,-3.5 -3.5,-3.5
Mechanical 13:
  lines w0.1: -3.5,-3.5 -3.5,3.5 3.5,3.5 3.5,-3.5 -3.5,-3.5
Mechanical 15:
  lines w0.1: -0.5,0 0.5,0 ; 0,-0.5 0,0.5 ; -4.5,-4.5 -4.5,4.5 4.5,4.5 4.5,-4.5 -4.5,-4.5
3D body: height 0, standoff 0, extent -3.5,-3.5 3.5,3.5

## BGA100P6X6-36 [mm] "BGA, 36-Leads, Body 7x7mm, Pitch 1mm"
height 3.5
pads (36):
  round 0.5 smd: A1(-2.5,2.5) A2(-1.5,2.5) A3(-0.5,2.5) A4(0.5,2.5) A5(1.5,2.5) A6(2.5,2.5) B1(-2.5,1.5) B2(-1.5,1.5) B3(-0.5,1.5) B4(0.5,1.5) B5(1.5,1.5) B6(2.5,1.5) C1(-2.5,0.5) C2(-1.5,0.5) C3(-0.5,0.5) C4(0.5,0.5) C5(1.5,0.5) C6(2.5,0.5) D1(-2.5,-0.5) D2(-1.5,-0.5) D3(-0.5,-0.5) D4(0.5,-0.5) D5(1.5,-0.5) D6(2.5,-0.5) E1(-2.5,-1.5) E2(-1.5,-1.5) E3(-0.5,-1.5) E4(0.5,-1.5) E5(1.5,-1.5) E6(2.5,-1.5) F1(-2.5,-2.5) F2(-1.5,-2.5) F3(-0.5,-2.5) F4(0.5,-2.5) F5(1.5,-2.5) F6(2.5,-2.5)
Top Overlay:
  circle w0.25: c-4.15,2.5 r0.125
  region: -2.5,3.5 -3.5,2.5 -3.5,3.5
  lines w0.2: -3.5,2.5 -2.5,3.5 ; -3.5,-3.5 3.5,-3.5 3.5,3.5 -3.5,3.5 -3.5,-3.5
Mechanical 13:
  lines w0.1: -3.5,-3.5 3.5,-3.5 3.5,3.5 -3.5,3.5 -3.5,-3.5
Mechanical 15:
  lines w0.1: -0.5,0 0.5,0 ; 0,-0.5 0,0.5 ; -4.5,-4.5 4.5,-4.5 4.5,4.5 -4.5,4.5 -4.5,-4.5
3D body: height 0, standoff 0, extent -3.5,-3.5 3.5,3.5

## BGA100P6X6-36A [mm] "BGA, 36-Leads, Body 8x8mm, Pitch 1mm"
height 3.5
pads (36):
  round 0.5 smd: A1(-2.5,2.5) A2(-1.5,2.5) A3(-0.5,2.5) A4(0.5,2.5) A5(1.5,2.5) A6(2.5,2.5) B1(-2.5,1.5) B2(-1.5,1.5) B3(-0.5,1.5) B4(0.5,1.5) B5(1.5,1.5) B6(2.5,1.5) C1(-2.5,0.5) C2(-1.5,0.5) C3(-0.5,0.5) C4(0.5,0.5) C5(1.5,0.5) C6(2.5,0.5) D1(-2.5,-0.5) D2(-1.5,-0.5) D3(-0.5,-0.5) D4(0.5,-0.5) D5(1.5,-0.5) D6(2.5,-0.5) E1(-2.5,-1.5) E2(-1.5,-1.5) E3(-0.5,-1.5) E4(0.5,-1.5) E5(1.5,-1.5) E6(2.5,-1.5) F1(-2.5,-2.5) F2(-1.5,-2.5) F3(-0.5,-2.5) F4(0.5,-2.5) F5(1.5,-2.5) F6(2.5,-2.5)
Top Overlay:
  circle w0.25: c-4.65,2.5 r0.125
  region: -3,4 -4,3 -4,4
  lines w0.2: -4,3 -3,4 ; -4,-4 -4,4 4,4 4,-4 -4,-4
Mechanical 13:
  lines w0.1: -4,-4 -4,4 4,4 4,-4 -4,-4
Mechanical 15:
  lines w0.1: -0.5,0 0.5,0 ; 0,-0.5 0,0.5 ; -5,-5 -5,5 5,5 5,-5 -5,-5
3D body: height 0, standoff 0, extent -4,-4 4,4

## BGA100P7X7-49 [mm] "BGA, 49-Leads, Body 8x8mm, Pitch 1mm"
height 3.5
pads (49):
  round 0.5 smd: A1(-3,3) A2(-2,3) A3(-1,3) A4(0,3) A5(1,3) A6(2,3) A7(3,3) B1(-3,2) B2(-2,2) B3(-1,2) B4(0,2) B5(1,2) B6(2,2) B7(3,2) C1(-3,1) C2(-2,1) C3(-1,1) C4(0,1) C5(1,1) C6(2,1) C7(3,1) D1(-3,0) D2(-2,0) D3(-1,0) D4(0,0) D5(1,0) D6(2,0) D7(3,0) E1(-3,-1) E2(-2,-1) E3(-1,-1) E4(0,-1) E5(1,-1) E6(2,-1) E7(3,-1) F1(-3,-2) F2(-2,-2) F3(-1,-2) F4(0,-2) F5(1,-2) F6(2,-2) F7(3,-2) G1(-3,-3) G2(-2,-3) G3(-1,-3) G4(0,-3) G5(1,-3) G6(2,-3) G7(3,-3)
Top Overlay:
  circle w0.25: c-4.65,3 r0.125
  region: -3,4 -4,3 -4,4
  lines w0.2: -4,3 -3,4 ; -4,-4 4,-4 4,4 -4,4 -4,-4
Mechanical 13:
  lines w0.1: -4,-4 4,-4 4,4 -4,4 -4,-4
Mechanical 15:
  lines w0.1: -0.5,0 0.5,0 ; 0,-0.5 0,0.5 ; -5,-5 5,-5 5,5 -5,5 -5,-5
3D body: height 0, standoff 0, extent -4,-4 4,4

## BGA100P7X7-49A [mm] "BGA, 49-Leads, Body 9x9mm, Pitch 1mm"
height 3.5
pads (49):
  round 0.5 smd: A1(-3,3) A2(-2,3) A3(-1,3) A4(0,3) A5(1,3) A6(2,3) A7(3,3) B1(-3,2) B2(-2,2) B3(-1,2) B4(0,2) B5(1,2) B6(2,2) B7(3,2) C1(-3,1) C2(-2,1) C3(-1,1) C4(0,1) C5(1,1) C6(2,1) C7(3,1) D1(-3,0) D2(-2,0) D3(-1,0) D4(0,0) D5(1,0) D6(2,0) D7(3,0) E1(-3,-1) E2(-2,-1) E3(-1,-1) E4(0,-1) E5(1,-1) E6(2,-1) E7(3,-1) F1(-3,-2) F2(-2,-2) F3(-1,-2) F4(0,-2) F5(1,-2) F6(2,-2) F7(3,-2) G1(-3,-3) G2(-2,-3) G3(-1,-3) G4(0,-3) G5(1,-3) G6(2,-3) G7(3,-3)
Top Overlay:
  circle w0.25: c-5.15,3 r0.125
  region: -3.5,4.5 -4.5,3.5 -4.5,4.5
  lines w0.2: -4.5,3.5 -3.5,4.5 ; -4.5,-4.5 -4.5,4.5 4.5,4.5 4.5,-4.5 -4.5,-4.5
Mechanical 13:
  lines w0.1: -4.5,-4.5 -4.5,4.5 4.5,4.5 4.5,-4.5 -4.5,-4.5
Mechanical 15:
  lines w0.1: -0.5,0 0.5,0 ; 0,-0.5 0,0.5 ; -5.5,-5.5 -5.5,5.5 5.5,5.5 5.5,-5.5 -5.5,-5.5
3D body: height 0, standoff 0, extent -4.5,-4.5 4.5,4.5

## BGA100P8X8-64 [mm] "BGA, 64-Leads, Body 9x9mm, Pitch 1mm"
height 3.5
pads (64):
  round 0.5 smd: A1(-3.5,3.5) A2(-2.5,3.5) A3(-1.5,3.5) A4(-0.5,3.5) A5(0.5,3.5) A6(1.5,3.5) A7(2.5,3.5) A8(3.5,3.5) B1(-3.5,2.5) B2(-2.5,2.5) B3(-1.5,2.5) B4(-0.5,2.5) B5(0.5,2.5) B6(1.5,2.5) B7(2.5,2.5) B8(3.5,2.5) C1(-3.5,1.5) C2(-2.5,1.5) C3(-1.5,1.5) C4(-0.5,1.5) C5(0.5,1.5) C6(1.5,1.5) C7(2.5,1.5) C8(3.5,1.5) D1(-3.5,0.5) D2(-2.5,0.5) D3(-1.5,0.5) D4(-0.5,0.5) D5(0.5,0.5) D6(1.5,0.5) D7(2.5,0.5) D8(3.5,0.5) E1(-3.5,-0.5) E2(-2.5,-0.5) E3(-1.5,-0.5) E4(-0.5,-0.5) E5(0.5,-0.5) E6(1.5,-0.5) E7(2.5,-0.5) E8(3.5,-0.5) F1(-3.5,-1.5) F2(-2.5,-1.5) F3(-1.5,-1.5) F4(-0.5,-1.5) F5(0.5,-1.5) F6(1.5,-1.5) F7(2.5,-1.5) F8(3.5,-1.5) G1(-3.5,-2.5) G2(-2.5,-2.5) G3(-1.5,-2.5) G4(-0.5,-2.5) G5(0.5,-2.5) G6(1.5,-2.5) G7(2.5,-2.5) G8(3.5,-2.5) H1(-3.5,-3.5) H2(-2.5,-3.5) H3(-1.5,-3.5) H4(-0.5,-3.5) H5(0.5,-3.5) H6(1.5,-3.5) H7(2.5,-3.5) H8(3.5,-3.5)
Top Overlay:
  circle w0.25: c-5.15,3.5 r0.125
  region: -3.5,4.5 -4.5,3.5 -4.5,4.5
  lines w0.2: -4.5,3.5 -3.5,4.5 ; -4.5,-4.5 4.5,-4.5 4.5,4.5 -4.5,4.5 -4.5,-4.5
Mechanical 13:
  lines w0.1: -4.5,-4.5 4.5,-4.5 4.5,4.5 -4.5,4.5 -4.5,-4.5
Mechanical 15:
  lines w0.1: -0.5,0 0.5,0 ; 0,-0.5 0,0.5 ; -5.5,-5.5 5.5,-5.5 5.5,5.5 -5.5,5.5 -5.5,-5.5
3D body: height 0, standoff 0, extent -4.5,-4.5 4.5,4.5

## BGA100P8X8-64A [mm] "BGA, 64-Leads, Body 13x11mm, Pitch 1mm"
height 1.2
pads (64):
  round 0.35 smd: A1(-3.5,3.5) A2(-2.5,3.5) A3(-1.5,3.5) A4(-0.5,3.5) A5(0.5,3.5) A6(1.5,3.5) A7(2.5,3.5) A8(3.5,3.5) B1(-3.5,2.5) B2(-2.5,2.5) B3(-1.5,2.5) B4(-0.5,2.5) B5(0.5,2.5) B6(1.5,2.5) B7(2.5,2.5) B8(3.5,2.5) C1(-3.5,1.5) C2(-2.5,1.5) C3(-1.5,1.5) C4(-0.5,1.5) C5(0.5,1.5) C6(1.5,1.5) C7(2.5,1.5) C8(3.5,1.5) D1(-3.5,0.5) D2(-2.5,0.5) D3(-1.5,0.5) D4(-0.5,0.5) D5(0.5,0.5) D6(1.5,0.5) D7(2.5,0.5) D8(3.5,0.5) E1(-3.5,-0.5) E2(-2.5,-0.5) E3(-1.5,-0.5) E4(-0.5,-0.5) E5(0.5,-0.5) E6(1.5,-0.5) E7(2.5,-0.5) E8(3.5,-0.5) F1(-3.5,-1.5) F2(-2.5,-1.5) F3(-1.5,-1.5) F4(-0.5,-1.5) F5(0.5,-1.5) F6(1.5,-1.5) F7(2.5,-1.5) F8(3.5,-1.5) G1(-3.5,-2.5) G2(-2.5,-2.5) G3(-1.5,-2.5) G4(-0.5,-2.5) G5(0.5,-2.5) G6(1.5,-2.5) G7(2.5,-2.5) G8(3.5,-2.5) H1(-3.5,-3.5) H2(-2.5,-3.5) H3(-1.5,-3.5) H4(-0.5,-3.5) H5(0.5,-3.5) H6(1.5,-3.5) H7(2.5,-3.5) H8(3.5,-3.5)
Top Overlay:
  circle w0.25: c-5.6,3.4 r0.125
  region: -4,6.4 -5,5.4 -5,6.4
  lines w0.2: -5,5.4 -4,6.4 ; -5,-6.6 5,-6.6 5,6.4 -5,6.4 -5,-6.6
Mechanical 13:
  lines w0.1: -5,-6.6 5,-6.6 5,6.4 -5,6.4 -5,-6.6
Mechanical 15:
  lines w0.1: -0.5,0 0.5,0 ; 0,-0.5 0,0.5 ; -6,-7.6 6,-7.6 6,7.4 -6,7.4 -6,-7.6
3D body: height 1.2, standoff 0, extent -4.999,-6.599 4.999,6.399

## BGA100P8X8-64A - duplicate [mm] "BGA, 64-Leads, Body 10x10mm, Pitch 1mm"
height 3.5
pads (64):
  round 0.5 smd: A1(-3.5,3.5) A2(-2.5,3.5) A3(-1.5,3.5) A4(-0.5,3.5) A5(0.5,3.5) A6(1.5,3.5) A7(2.5,3.5) A8(3.5,3.5) B1(-3.5,2.5) B2(-2.5,2.5) B3(-1.5,2.5) B4(-0.5,2.5) B5(0.5,2.5) B6(1.5,2.5) B7(2.5,2.5) B8(3.5,2.5) C1(-3.5,1.5) C2(-2.5,1.5) C3(-1.5,1.5) C4(-0.5,1.5) C5(0.5,1.5) C6(1.5,1.5) C7(2.5,1.5) C8(3.5,1.5) D1(-3.5,0.5) D2(-2.5,0.5) D3(-1.5,0.5) D4(-0.5,0.5) D5(0.5,0.5) D6(1.5,0.5) D7(2.5,0.5) D8(3.5,0.5) E1(-3.5,-0.5) E2(-2.5,-0.5) E3(-1.5,-0.5) E4(-0.5,-0.5) E5(0.5,-0.5) E6(1.5,-0.5) E7(2.5,-0.5) E8(3.5,-0.5) F1(-3.5,-1.5) F2(-2.5,-1.5) F3(-1.5,-1.5) F4(-0.5,-1.5) F5(0.5,-1.5) F6(1.5,-1.5) F7(2.5,-1.5) F8(3.5,-1.5) G1(-3.5,-2.5) G2(-2.5,-2.5) G3(-1.5,-2.5) G4(-0.5,-2.5) G5(0.5,-2.5) G6(1.5,-2.5) G7(2.5,-2.5) G8(3.5,-2.5) H1(-3.5,-3.5) H2(-2.5,-3.5) H3(-1.5,-3.5) H4(-0.5,-3.5) H5(0.5,-3.5) H6(1.5,-3.5) H7(2.5,-3.5) H8(3.5,-3.5)
Top Overlay:
  circle w0.25: c-5.65,3.5 r0.125
  region: -4,5 -5,4 -5,5
  lines w0.2: -5,4 -4,5 ; -5,-5 -5,5 5,5 5,-5 -5,-5
Mechanical 13:
  lines w0.1: -5,-5 -5,5 5,5 5,-5 -5,-5
Mechanical 15:
  lines w0.1: -0.5,0 0.5,0 ; 0,-0.5 0,0.5 ; -6,-6 -6,6 6,6 6,-6 -6,-6
3D body: height 0, standoff 0, extent -5,-5 5,5

## BGA100P8X8-64B [mm] "64-Ball Fortified Ball Grid Array Rectangular 1 mm Pitch"
height 1.4
pads (64):
  round 0.5 smd: A1(-3.5,3.5) A2(-2.5,3.5) A3(-1.5,3.5) A4(-0.5,3.5) A5(0.5,3.5) A6(1.5,3.5) A7(2.5,3.5) A8(3.5,3.5) B1(-3.5,2.5) B2(-2.5,2.5) B3(-1.5,2.5) B4(-0.5,2.5) B5(0.5,2.5) B6(1.5,2.5) B7(2.5,2.5) B8(3.5,2.5) C1(-3.5,1.5) C2(-2.5,1.5) C3(-1.5,1.5) C4(-0.5,1.5) C5(0.5,1.5) C6(1.5,1.5) C7(2.5,1.5) C8(3.5,1.5) D1(-3.5,0.5) D2(-2.5,0.5) D3(-1.5,0.5) D4(-0.5,0.5) D5(0.5,0.5) D6(1.5,0.5) D7(2.5,0.5) D8(3.5,0.5) E1(-3.5,-0.5) E2(-2.5,-0.5) E3(-1.5,-0.5) E4(-0.5,-0.5) E5(0.5,-0.5) E6(1.5,-0.5) E7(2.5,-0.5) E8(3.5,-0.5) F1(-3.5,-1.5) F2(-2.5,-1.5) F3(-1.5,-1.5) F4(-0.5,-1.5) F5(0.5,-1.5) F6(1.5,-1.5) F7(2.5,-1.5) F8(3.5,-1.5) G1(-3.5,-2.5) G2(-2.5,-2.5) G3(-1.5,-2.5) G4(-0.5,-2.5) G5(0.5,-2.5) G6(1.5,-2.5) G7(2.5,-2.5) G8(3.5,-2.5) H1(-3.5,-3.5) H2(-2.5,-3.5) H3(-1.5,-3.5) H4(-0.5,-3.5) H5(0.5,-3.5) H6(1.5,-3.5) H7(2.5,-3.5) H8(3.5,-3.5)
Top Overlay:
  circle w0.25: c-6.15,3.5 r0.125
  region: -4.5,6.5 -5.5,5.5 -5.5,6.5
  lines w0.2: -5.5,5.5 -4.5,6.5 ; -5.5,-6.5 5.5,-6.5 5.5,6.5 -5.5,6.5 -5.5,-6.5
Mechanical 13:
  lines w0.1: -5.5,-6.5 5.5,-6.5 5.5,6.5 -5.5,6.5 -5.5,-6.5
Mechanical 15:
  lines w0.1: -0.5,0 0.5,0 ; 0,-0.5 0,0.5 ; -6.5,-7.5 6.5,-7.5 6.5,7.5 -6.5,7.5 -6.5,-7.5
3D body: height 1.4, standoff 0, extent -5.499,-6.499 5.499,6.499

## BGA100P8X10-80 [mm] "80-Ball Fortified Ball Grid Array Rectangular 1 mm Pitch"
height 1.6
pads (80):
  round 0.5 smd: A1(-3.5,4.5) A2(-2.5,4.5) A3(-1.5,4.5) A4(-0.5,4.5) A5(0.5,4.5) A6(1.5,4.5) A7(2.5,4.5) A8(3.5,4.5) B1(-3.5,3.5) B2(-2.5,3.5) B3(-1.5,3.5) B4(-0.5,3.5) B5(0.5,3.5) B6(1.5,3.5) B7(2.5,3.5) B8(3.5,3.5) C1(-3.5,2.5) C2(-2.5,2.5) C3(-1.5,2.5) C4(-0.5,2.5) C5(0.5,2.5) C6(1.5,2.5) C7(2.5,2.5) C8(3.5,2.5) D1(-3.5,1.5) D2(-2.5,1.5) D3(-1.5,1.5) D4(-0.5,1.5) D5(0.5,1.5) D6(1.5,1.5) D7(2.5,1.5) D8(3.5,1.5) E1(-3.5,0.5) E2(-2.5,0.5) E3(-1.5,0.5) E4(-0.5,0.5) E5(0.5,0.5) E6(1.5,0.5) E7(2.5,0.5) E8(3.5,0.5) F1(-3.5,-0.5) F2(-2.5,-0.5) F3(-1.5,-0.5) F4(-0.5,-0.5) F5(0.5,-0.5) F6(1.5,-0.5) F7(2.5,-0.5) F8(3.5,-0.5) G1(-3.5,-1.5) G2(-2.5,-1.5) G3(-1.5,-1.5) G4(-0.5,-1.5) G5(0.5,-1.5) G6(1.5,-1.5) G7(2.5,-1.5) G8(3.5,-1.5) H1(-3.5,-2.5) H2(-2.5,-2.5) H3(-1.5,-2.5) H4(-0.5,-2.5) H5(0.5,-2.5) H6(1.5,-2.5) H7(2.5,-2.5) H8(3.5,-2.5) J1(-3.5,-3.5) J2(-2.5,-3.5) J3(-1.5,-3.5) J4(-0.5,-3.5) J5(0.5,-3.5) J6(1.5,-3.5) J7(2.5,-3.5) J8(3.5,-3.5) K1(-3.5,-4.5) K2(-2.5,-4.5) K3(-1.5,-4.5) K4(-0.5,-4.5) K5(0.5,-4.5) K6(1.5,-4.5) K7(2.5,-4.5) K8(3.5,-4.5)
Top Overlay:
  circle w0.25: c-6.15,4.5 r0.125
  region: -4.5,6.5 -5.5,5.5 -5.5,6.5
  lines w0.2: -5.5,5.5 -4.5,6.5 ; -5.5,-6.5 -5.5,6.5 5.5,6.5 5.5,-6.5 -5.5,-6.5
Mechanical 13:
  lines w0.1: -5.5,-6.5 -5.5,6.5 5.5,6.5 5.5,-6.5 -5.5,-6.5
Mechanical 15:
  lines w0.1: -0.5,0 0.5,0 ; 0,-0.5 0,0.5 ; -6.5,-7.5 -6.5,7.5 6.5,7.5 6.5,-7.5 -6.5,-7.5
3D body: height 1.6, standoff 0, extent -5.5,-6.5 5.5,6.5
